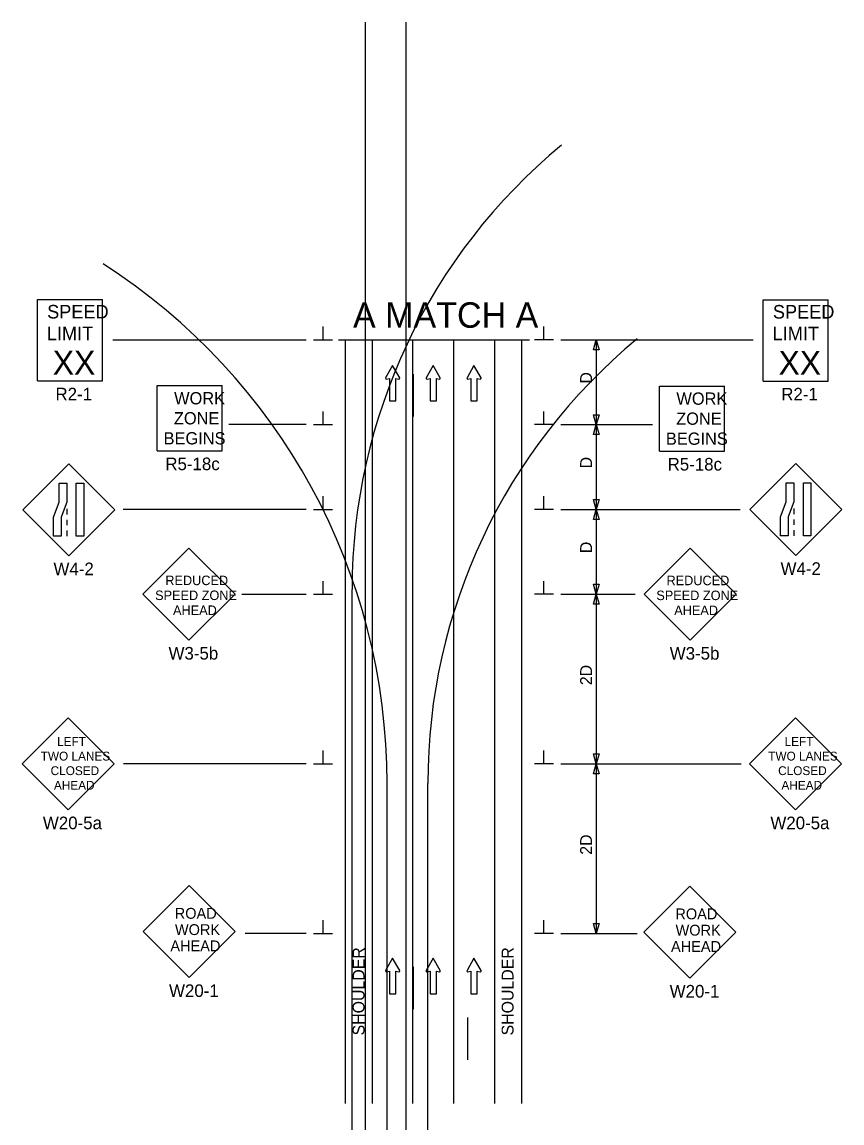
# Model space of a CAD drawing. Extents: x 16452 to 19508, y 5713 to 7079.
# Drawn here: x 17852 to 18336, y 6430 to 7079 of the extents above; entities that cross this region are included whole.
import ezdxf

# ---------------------------------------------------------------- set-up
doc = ezdxf.new("R2010")
doc.units = 0
for name, color, linetype in [('ALI_LEGAL_EX', 7, 'Continuous'), ('MT_SCRATCH_LEVEL_E', 7, 'Continuous'), ('PAVT_EDGE_EX', 7, 'Continuous'), ('TRAFFIC_SIGNS_PR', 7, 'Continuous'), ('TYPICAL_TEXT_DIMEN_PR', 7, 'Continuous')]:
    doc.layers.add(name, color=color, linetype=linetype)

msp = doc.modelspace()

# ---------------------------------------------------------------- linework, layer by layer
at = {"layer": 'ALI_LEGAL_EX'}
for p, q in [((18054.48, 7078.99), (18054.48, 6260.86)), ((18078.48, 7078.99), (18078.48, 6260.86)), ((18054.48, 6981.91), (18054.48, 6118)), ((18078.48, 6981.91), (18078.48, 6118)), ((18082.72, 6441.2), (18082.72, 6891.55)), ((18106.72, 6441.2), (18106.72, 6891.55)), ((18046.81, 6243.91), (18046.81, 6744.25)), ((18067.45, 6129.67), (18067.45, 6630.02)), ((18091.45, 6129.67), (18091.45, 6630.02))]:
    msp.add_line(p, q, dxfattribs=at)
for points in [[(18082.81, 6871.42), (18082.81, 6846.42)], [(18082.72, 6841.2), (18082.72, 6866.2)], [(18106.72, 6841.2), (18106.72, 6866.2)], [(18082.72, 6741.2), (18082.72, 6766.2)], [(18106.72, 6741.2), (18106.72, 6766.2)], [(18082.72, 6641.2), (18082.72, 6666.2)], [(18106.72, 6641.2), (18106.72, 6666.2)], [(18082.72, 6541.2), (18082.72, 6566.2)], [(18106.72, 6541.2), (18106.72, 6566.2)], [(18082.81, 6521.86), (18082.81, 6496.86)], [(18114.95, 6491.99), (18114.95, 6466.99)], [(18082.72, 6441.2), (18082.72, 6466.2)], [(18106.72, 6441.2), (18106.72, 6466.2)]]:
    msp.add_lwpolyline(points, dxfattribs=at)
for centre, radius, start, end in [((18386.81, 6744.25), 340, 129.56655, 180), ((17703.45, 6630.02), 364, 0, 57.29578), ((18431.45, 6630.02), 340, 129.56655, 180)]:
    msp.add_arc(centre, radius, start, end, dxfattribs=at)
at = {"layer": 'MT_SCRATCH_LEVEL_E'}
for p, q in [((18070.73, 6876.38), (18066.62, 6869.14)), ((18074.88, 6869.14), (18070.73, 6876.38)), ((18094.64, 6876.38), (18090.53, 6869.14)), ((18098.78, 6869.14), (18094.64, 6876.38)), ((18118.69, 6876.38), (18114.58, 6869.14)), ((18122.84, 6869.14), (18118.69, 6876.38)), ((18067.1, 6868.46), (18068.88, 6868.77)), ((18068.88, 6868.77), (18068.88, 6855.51)), ((18072.62, 6855.51), (18072.62, 6868.77)), ((18072.62, 6868.77), (18074.4, 6868.46)), ((18091.01, 6868.46), (18092.78, 6868.77)), ((18092.78, 6868.77), (18092.78, 6855.51)), ((18096.53, 6855.51), (18096.53, 6868.77)), ((18096.53, 6868.77), (18098.3, 6868.46)), ((18115.06, 6868.46), (18116.84, 6868.77)), ((18116.84, 6868.77), (18116.84, 6855.51)), ((18120.58, 6855.51), (18120.58, 6868.77)), ((18120.58, 6868.77), (18122.36, 6868.46)), ((18068.88, 6855.51), (18072.62, 6855.51)), ((18092.78, 6855.51), (18096.53, 6855.51)), ((18116.84, 6855.51), (18120.58, 6855.51)), ((18070.73, 6526.83), (18066.62, 6519.59)), ((18074.88, 6519.59), (18070.73, 6526.83)), ((18094.64, 6526.83), (18090.53, 6519.59)), ((18098.78, 6519.59), (18094.64, 6526.83)), ((18118.69, 6526.83), (18114.58, 6519.59)), ((18122.84, 6519.59), (18118.69, 6526.83)), ((18067.1, 6518.9), (18068.88, 6519.22)), ((18068.88, 6519.22), (18068.88, 6505.96)), ((18072.62, 6505.96), (18072.62, 6519.22)), ((18072.62, 6519.22), (18074.4, 6518.9)), ((18091.01, 6518.9), (18092.78, 6519.22)), ((18092.78, 6519.22), (18092.78, 6505.96)), ((18096.53, 6505.96), (18096.53, 6519.22)), ((18096.53, 6519.22), (18098.3, 6518.9)), ((18115.06, 6518.9), (18116.84, 6519.22)), ((18116.84, 6519.22), (18116.84, 6505.96)), ((18120.58, 6505.96), (18120.58, 6519.22)), ((18120.58, 6519.22), (18122.36, 6518.9)), ((18068.88, 6505.96), (18072.62, 6505.96)), ((18092.78, 6505.96), (18096.53, 6505.96)), ((18116.84, 6505.96), (18120.58, 6505.96))]:
    msp.add_line(p, q, dxfattribs=at)
for centre, start, end in [((18067.03, 6868.91), 150.42484, 279.96381), ((18074.47, 6868.91), 260.03619, 29.77312), ((18090.93, 6868.91), 150.42484, 279.96381), ((18098.37, 6868.91), 260.03619, 29.77312), ((18114.99, 6868.91), 150.42484, 279.96381), ((18122.43, 6868.91), 260.03619, 29.77312), ((18067.03, 6519.36), 150.42484, 279.96381), ((18074.47, 6519.36), 260.03619, 29.77312), ((18090.93, 6519.36), 150.42484, 279.96381), ((18098.37, 6519.36), 260.03619, 29.77312), ((18114.99, 6519.36), 150.42484, 279.96381), ((18122.43, 6519.36), 260.03619, 29.77312)]:
    msp.add_arc(centre, 0.463, start, end, dxfattribs=at)
at = {"layer": 'PAVT_EDGE_EX'}
for p, q in [((18042.72, 6891.55), (18042.72, 6441.2)), ((18058.72, 6891.55), (18058.72, 6441.2)), ((18130.72, 6891.55), (18130.72, 6441.2)), ((18146.72, 6891.55), (18146.72, 6441.2))]:
    msp.add_line(p, q, dxfattribs=at)
at = {"layer": 'TRAFFIC_SIGNS_PR'}
for p, q in [((17861.28, 6915.3), (17899.68, 6915.3)), ((17861.28, 6867.3), (17861.28, 6915.3)), ((17899.68, 6867.3), (17899.68, 6915.3)), ((18289.14, 6915.25), (18327.54, 6915.25)), ((18289.14, 6867.25), (18289.14, 6915.25)), ((18327.54, 6867.25), (18327.54, 6915.25)), ((17861.28, 6867.3), (17899.68, 6867.3)), ((17931.91, 6826.15), (17931.91, 6864.55)), ((17931.91, 6864.55), (17970.31, 6864.55)), ((17970.31, 6826.15), (17970.31, 6864.55)), ((18228.02, 6825.93), (18228.02, 6864.33)), ((18228.02, 6864.33), (18266.42, 6864.33)), ((18266.42, 6825.93), (18266.42, 6864.33)), ((18289.14, 6867.25), (18327.54, 6867.25)), ((17931.91, 6826.15), (17970.31, 6826.15)), ((18228.02, 6825.93), (18266.42, 6825.93)), ((17879.82, 6818.51), (17852.66, 6791.36)), ((17906.97, 6791.36), (17879.82, 6818.51)), ((18308.47, 6818.7), (18281.32, 6791.55)), ((18335.62, 6791.55), (18308.47, 6818.7)), ((17852.66, 6791.36), (17879.82, 6764.21)), ((17878.57, 6791.85), (17878.57, 6788.65)), ((17879.82, 6764.21), (17906.97, 6791.36)), ((18281.32, 6791.55), (18308.47, 6764.39)), ((18307.22, 6792.04), (18307.22, 6788.84)), ((18308.47, 6764.39), (18335.62, 6791.55)), ((17878.57, 6785.45), (17878.57, 6782.25)), ((18307.22, 6785.64), (18307.22, 6782.44)), ((17878.57, 6779.05), (17878.57, 6775.85)), ((18307.22, 6779.24), (18307.22, 6776.04)), ((17950.66, 6768.77), (17923.51, 6741.62)), ((17977.82, 6741.62), (17950.66, 6768.77)), ((18246.12, 6768.73), (18218.97, 6741.57)), ((18273.28, 6741.57), (18246.12, 6768.73)), ((17923.51, 6741.62), (17950.66, 6714.46)), ((17950.66, 6714.46), (17977.82, 6741.62)), ((18218.97, 6741.57), (18246.12, 6714.42)), ((18246.12, 6714.42), (18273.28, 6741.57)), ((17879.4, 6668.7), (17852.25, 6641.55)), ((17906.55, 6641.55), (17879.4, 6668.7)), ((18308.29, 6668.7), (18281.13, 6641.55)), ((18335.44, 6641.55), (18308.29, 6668.7)), ((17852.25, 6641.55), (17879.4, 6614.4)), ((17879.4, 6614.4), (17906.55, 6641.55)), ((18281.13, 6641.55), (18308.29, 6614.4)), ((18308.29, 6614.4), (18335.44, 6641.55)), ((17950.74, 6569.77), (17923.59, 6542.62)), ((17977.9, 6542.62), (17950.74, 6569.77)), ((18245.88, 6569.45), (18218.73, 6542.3)), ((18273.03, 6542.3), (18245.88, 6569.45)), ((17923.59, 6542.62), (17950.74, 6515.47)), ((17950.74, 6515.47), (17977.9, 6542.62)), ((18218.73, 6542.3), (18245.88, 6515.14)), ((18245.88, 6515.14), (18273.03, 6542.3))]:
    msp.add_line(p, q, dxfattribs=at)
for points in [[(17878.57, 6807.09), (17878.57, 6795.91), (17875.23, 6787.03), (17875.23, 6775.85), (17870.73, 6775.85), (17870.73, 6787.03), (17874.08, 6795.91), (17874.08, 6807.09)], [(17888.71, 6807.09), (17888.71, 6775.85), (17884.21, 6775.85), (17884.21, 6807.09)], [(18307.22, 6807.28), (18307.22, 6796.1), (18303.88, 6787.22), (18303.88, 6776.04), (18299.39, 6776.04), (18299.39, 6787.22), (18302.73, 6796.1), (18302.73, 6807.28)], [(18317.36, 6807.28), (18317.36, 6776.04), (18312.87, 6776.04), (18312.87, 6807.28)]]:
    msp.add_lwpolyline(points, close=True, dxfattribs=at)
at = {"layer": 'TYPICAL_TEXT_DIMEN_PR'}
for p, q in [((18029.69, 6891.55), (18029.69, 6899.34)), ((18159.94, 6891.55), (18159.94, 6899.34)), ((17905.71, 6891.55), (18019.81, 6891.55)), ((18024.06, 6891.55), (18035.31, 6891.55)), ((18038.79, 6891.55), (18151.44, 6891.55)), ((18165.56, 6891.55), (18154.31, 6891.55)), ((18169.81, 6891.55), (18283.27, 6891.55)), ((18189.24, 6885.69), (18190.81, 6891.55)), ((18190.81, 6891.55), (18190.81, 6841.55)), ((18190.81, 6891.55), (18192.39, 6885.69)), ((18190.81, 6885.69), (18189.24, 6885.69)), ((18192.39, 6885.69), (18190.81, 6885.69)), ((18029.69, 6841.55), (18029.69, 6849.34)), ((18159.94, 6841.55), (18159.94, 6849.34)), ((18190.81, 6841.55), (18189.24, 6847.41)), ((18189.24, 6847.41), (18190.81, 6847.41)), ((18190.81, 6847.41), (18192.39, 6847.41)), ((18192.39, 6847.41), (18190.81, 6841.55)), ((18019.81, 6841.55), (17974.13, 6841.55)), ((18024.06, 6841.55), (18035.31, 6841.55)), ((18165.56, 6841.55), (18154.31, 6841.55)), ((18169.81, 6841.55), (18223.86, 6841.55)), ((18189.24, 6835.69), (18190.81, 6841.55)), ((18190.81, 6841.55), (18192.39, 6835.69)), ((18190.81, 6841.55), (18190.81, 6791.55)), ((18190.81, 6835.69), (18189.24, 6835.69)), ((18192.39, 6835.69), (18190.81, 6835.69)), ((18029.69, 6791.55), (18029.69, 6799.34)), ((18159.94, 6791.55), (18159.94, 6799.34)), ((18019.81, 6791.55), (17911.86, 6791.55)), ((18024.06, 6791.55), (18035.31, 6791.55)), ((18165.56, 6791.55), (18154.31, 6791.55)), ((18169.81, 6791.55), (18275.59, 6791.55)), ((18190.81, 6791.55), (18189.24, 6797.41)), ((18189.24, 6797.41), (18190.81, 6797.41)), ((18189.24, 6785.69), (18190.81, 6791.55)), ((18190.81, 6797.41), (18192.39, 6797.41)), ((18192.39, 6797.41), (18190.81, 6791.55)), ((18190.81, 6791.55), (18190.81, 6741.55)), ((18190.81, 6791.55), (18192.39, 6785.69)), ((18190.81, 6785.69), (18189.24, 6785.69)), ((18192.39, 6785.69), (18190.81, 6785.69)), ((18029.69, 6741.55), (18029.69, 6749.34)), ((18159.94, 6741.55), (18159.94, 6749.34)), ((18190.81, 6741.55), (18189.24, 6747.41)), ((18189.24, 6747.41), (18190.81, 6747.41)), ((18190.81, 6747.41), (18192.39, 6747.41)), ((18192.39, 6747.41), (18190.81, 6741.55)), ((17981.9, 6741.55), (18019.81, 6741.55)), ((18024.06, 6741.55), (18035.31, 6741.55)), ((18165.56, 6741.55), (18154.31, 6741.55)), ((18169.81, 6741.55), (18213.72, 6741.55)), ((18189.24, 6735.69), (18190.81, 6741.55)), ((18190.81, 6741.55), (18190.81, 6641.55)), ((18190.81, 6741.55), (18192.39, 6735.69)), ((18190.81, 6735.69), (18189.24, 6735.69)), ((18192.39, 6735.69), (18190.81, 6735.69)), ((18029.69, 6641.55), (18029.69, 6649.34)), ((18159.94, 6641.55), (18159.94, 6649.34)), ((18190.81, 6641.55), (18189.24, 6647.41)), ((18189.24, 6647.41), (18190.81, 6647.41)), ((18190.81, 6647.41), (18192.39, 6647.41)), ((18192.39, 6647.41), (18190.81, 6641.55)), ((18019.81, 6641.55), (17912.11, 6641.55)), ((18024.06, 6641.55), (18035.31, 6641.55)), ((18165.56, 6641.55), (18154.31, 6641.55)), ((18169.81, 6641.55), (18276.26, 6641.55)), ((18189.24, 6635.69), (18190.81, 6641.55)), ((18190.81, 6635.69), (18189.24, 6635.69)), ((18190.81, 6641.55), (18190.81, 6541.55)), ((18190.81, 6641.55), (18192.39, 6635.69)), ((18192.39, 6635.69), (18190.81, 6635.69)), ((18029.69, 6541.55), (18029.69, 6549.34)), ((18159.94, 6541.55), (18159.94, 6549.34)), ((18190.81, 6541.55), (18189.24, 6547.41)), ((18189.24, 6547.41), (18190.81, 6547.41)), ((18190.81, 6547.41), (18192.39, 6547.41)), ((18192.39, 6547.41), (18190.81, 6541.55)), ((18019.81, 6541.55), (17983.81, 6541.55)), ((18024.06, 6541.55), (18035.31, 6541.55)), ((18165.56, 6541.55), (18154.31, 6541.55)), ((18169.81, 6541.55), (18214.92, 6541.55))]:
    msp.add_line(p, q, dxfattribs=at)

# ---------------------------------------------------------------- texts
at = {"layer": 'TRAFFIC_SIGNS_PR'}
for s, height, p in [('SPEED', 8, (17867.05, 6904.16)), ('SPEED', 8, (18294.91, 6904.12)), ('LIMIT', 8, (17866.89, 6891.36)), ('LIMIT', 8, (18294.75, 6891.32)), ('XX', 14.031, (17870.39, 6871.06)), ('XX', 14.031, (18298.25, 6871.01)), ('R2-1', 7.44, (17871.96, 6855.86)), ('R2-1', 7.44, (18299.82, 6855.81)), ('WORK', 7.217, (17941.91, 6853.52)), ('WORK', 7.217, (18238.02, 6853.3)), ('ZONE', 7.217, (17941.79, 6841.71)), ('ZONE', 7.217, (18237.9, 6841.49)), ('BEGINS', 7.217, (17935.72, 6829.9)), ('BEGINS', 7.217, (18231.83, 6829.68)), ('R5-18c', 7.44, (17936.72, 6814.71)), ('R5-18c', 7.44, (18232.83, 6814.49)), ('W4-2', 7.44, (17870.78, 6752.77)), ('W4-2', 7.44, (18299.43, 6752.95)), ('REDUCED', 5.6, (17936.72, 6746.92)), ('REDUCED', 5.6, (18232.18, 6746.88)), ('SPEED ZONE', 5.6, (17930.71, 6738.12)), ('SPEED ZONE', 5.6, (18226.18, 6738.08)), ('AHEAD', 5.6, (17941.27, 6729.32)), ('AHEAD', 5.6, (18236.74, 6729.28)), ('W3-5b', 7.44, (17938.62, 6703.02)), ('W3-5b', 7.44, (18234.08, 6702.98)), ('LEFT', 5.2, (17872.94, 6652.09)), ('LEFT', 5.2, (18301.82, 6652.09)), ('TWO LANES', 5.2, (17863.26, 6643.49)), ('TWO LANES', 5.2, (18292.15, 6643.49)), ('CLOSED', 5.2, (17869.11, 6634.89)), ('CLOSED', 5.2, (18298, 6634.89)), ('AHEAD', 5.2, (17871.06, 6626.29)), ('AHEAD', 5.2, (18299.94, 6626.29)), ('W20-5a', 7.44, (17864.54, 6602.96)), ('W20-5a', 7.44, (18293.42, 6602.96)), ('ROAD', 6.4, (17942.29, 6550.16)), ('ROAD', 6.4, (18237.42, 6549.83)), ('WORK', 6.4, (17942.39, 6540.56)), ('WORK', 6.4, (18237.53, 6540.23)), ('AHEAD', 6.4, (17939.7, 6530.96)), ('AHEAD', 6.4, (18234.84, 6530.63)), ('W20-1', 7.44, (17938.91, 6504.03)), ('W20-1', 7.44, (18234.05, 6503.7))]:
    msp.add_text(s, height=height, dxfattribs=at).set_placement(p)
at = {"layer": 'TYPICAL_TEXT_DIMEN_PR'}
msp.add_text('A MATCH A', height=15, dxfattribs=at).set_placement((18047.38, 6898.69))
for s, p in [('D', (18188.26, 6865.77)), ('D', (18188.26, 6815.77)), ('D', (18188.26, 6765.77)), ('2D', (18188.26, 6687.91)), ('2D', (18188.26, 6587.91)), ('SHOULDER', (18054.15, 6481.37)), ('SHOULDER', (18142.01, 6481.37))]:
    msp.add_text(s, height=7, rotation=90, dxfattribs=at).set_placement(p)

doc.saveas('drawing.dxf')
